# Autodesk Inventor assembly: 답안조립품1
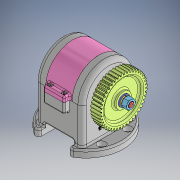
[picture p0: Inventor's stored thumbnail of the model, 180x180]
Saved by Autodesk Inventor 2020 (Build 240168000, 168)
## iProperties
Created: 2024-08
Part Number: 답안조립품1
Document SubType Name: Assembly
Designer: 1강의실14
Author: 1강의실14
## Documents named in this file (22)
- C:\Users\1강의실14\Desktop\740804V1011\답안조립품1.iam
- C:\Users\1강의실14\Desktop\740804V1011\본체.ipt
- C:\Users\1강의실14\Desktop\740804V1011\오일레스 부시 20 15.ipt
- C:\Users\1강의실14\Desktop\740804V1011\부시 커버.ipt
- C:\Users\1강의실14\Desktop\740804V1011\육각 소켓 머리 볼트 M4x10.ipt
- C:\Users\1강의실14\Desktop\740804V1011\링크.ipt
- C:\Users\1강의실14\Desktop\740804V1011\펀치.ipt
- C:\Users\1강의실14\Desktop\740804V1011\핀.ipt
- C:\Users\1강의실14\Desktop\740804V1011\E형 멈춤링 10-8.ipt
- C:\Users\1강의실14\Desktop\740804V1011\깊은 홈 볼 베어링 6904.ipt
- C:\Users\1강의실14\Desktop\740804V1011\칼라.ipt
- C:\Users\1강의실14\Desktop\740804V1011\편심축.ipt
- C:\Users\1강의실14\Desktop\740804V1011\뒷커버.ipt
- C:\Users\1강의실14\Desktop\740804V1011\오일실 20 32 5.ipt
- C:\Users\1강의실14\Desktop\740804V1011\앞커버.ipt
- C:\Users\1강의실14\Desktop\740804V1011\평행키 5x5x12.ipt
- C:\Users\1강의실14\Desktop\740804V1011\스퍼 기어.ipt
- C:\Users\1강의실14\Desktop\740804V1011\평와셔 M10.ipt
- C:\Users\1강의실14\Desktop\740804V1011\스프링 와셔 M10.ipt
- C:\Users\1강의실14\Desktop\740804V1011\육각 너트 M10x1.ipt
- C:\Users\1강의실14\Desktop\740804V1011\윗커버.ipt
- C:\Users\1강의실14\Desktop\740804V1011\육각 소켓 머리 볼트 M4x10_MIR.ipt
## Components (2 placed, 2 different names)
1. 핀:1
2. E형 멈춤링 10-8:4
